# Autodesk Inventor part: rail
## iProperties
Shininess: 64.0
Length Units: 11269
Angle Units: 11279
Time Units: 11290
Mass Units: 11283
Length Display Precision: 3
Angle Display Precision: 2
Compacted: True
Part Number: rail
Document SubType Name: Modeling
Created: 2005-02
Material: Par défaut
Designer: LEGERET Philippe
Density: 0.0
Volumn: 0.0
Area: 0.0
PropertySet Name: Model Information
Control State: 0
Master: False
Checked Out: False
Author: LEGERET Philippe
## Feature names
1. Extrusion1
